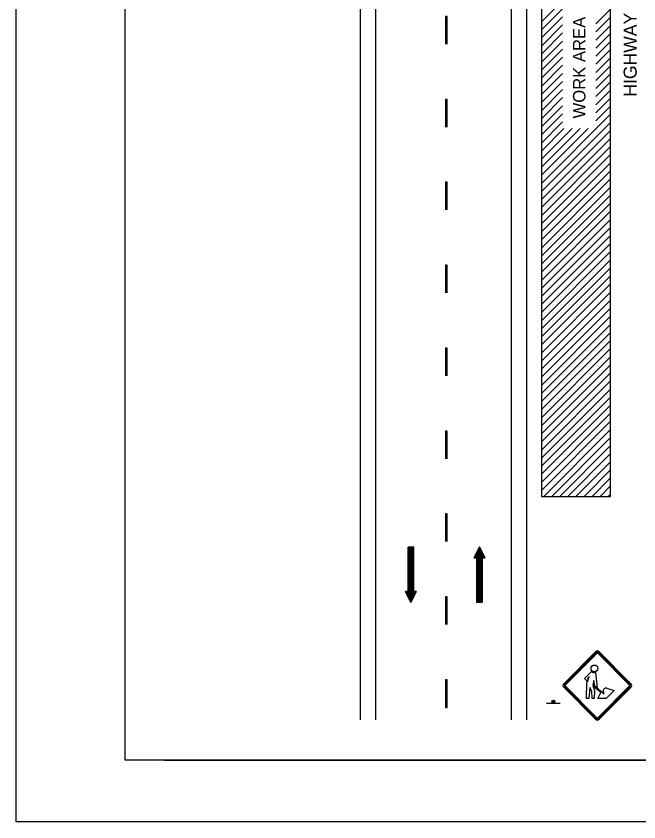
# Model space of a CAD drawing. Extents: x 1342 to 1558, y 178 to 457.
# Drawn here: x 1342.3 to 1451.3, y 177.9 to 318.9 of the extents above; entities that cross this region are included whole.
import ezdxf

# ---------------------------------------------------------------- set-up
doc = ezdxf.new("R2010")
doc.units = 0
for name, color, linetype in [('Level 1', 7, 'Continuous'), ('Level 10', 7, 'Continuous'), ('Level 2', 7, 'Continuous'), ('Level 22', 7, 'Continuous'), ('Level 44', 7, 'Continuous'), ('Level 60', 7, 'Continuous')]:
    doc.layers.add(name, color=color, linetype=linetype)

msp = doc.modelspace()

# ---------------------------------------------------------------- linework, layer by layer
at = {"layer": 'Level 1'}
for p, q in [((1443.76, 207.68), (1438.18, 202.11)), ((1443.88, 207.56), (1438.31, 201.99)), ((1444.01, 207.43), (1438.43, 201.86)), ((1449.72, 201.86), (1444.14, 207.43)), ((1449.84, 201.98), (1444.27, 207.56)), ((1449.96, 202.11), (1444.39, 207.68)), ((1443.81, 205.24), (1443.8, 205.24)), ((1438.43, 201.73), (1444, 196.15)), ((1444.14, 196.15), (1449.72, 201.72)), ((1438.18, 201.48), (1443.76, 195.9)), ((1438.31, 201.6), (1443.88, 196.03)), ((1444.26, 196.03), (1449.84, 201.6)), ((1444.39, 195.9), (1449.96, 201.47))]:
    msp.add_line(p, q, dxfattribs=at)
for points in [[(1442.35, 203.03), (1442.49, 202.92), (1442.33, 202.52), (1441.82, 202.99), (1443.04, 204.25)], [(1442.35, 203.03), (1442.49, 202.92), (1442.33, 202.52), (1441.82, 202.99), (1443.04, 204.25)], [(1442.77, 201.42), (1442.59, 199.52), (1442.16, 199.52), (1442.22, 202.25), (1442.33, 202.52), (1441.82, 202.99), (1443.04, 204.25)], [(1445.71, 201.3), (1446.99, 200.92), (1445.6, 199.52), (1444.15, 199.52), (1444.69, 200.58), (1443.28, 201.73), (1443.56, 201), (1443.52, 199.52), (1443.17, 199.52), (1443.11, 200.78), (1442.77, 201.42), (1442.59, 199.52), (1442.16, 199.52), (1442.22, 202.25), (1442.66, 203.35), (1442.35, 203.03)], [(1445.71, 201.3), (1446.99, 200.92), (1445.6, 199.52), (1444.15, 199.52), (1444.69, 200.58), (1443.28, 201.73), (1443.56, 201), (1443.52, 199.52), (1443.17, 199.52), (1443.11, 200.78), (1442.77, 201.42), (1442.59, 199.52), (1442.16, 199.52), (1442.22, 202.25), (1442.66, 203.35), (1442.35, 203.03)], [(1443.73, 204.07), (1444.02, 201.35), (1443.65, 201.65), (1443.45, 202.66), (1443.28, 201.96), (1445.27, 200.32), (1445.13, 200.67)], [(1443.73, 204.07), (1444.02, 201.35), (1443.65, 201.65), (1443.45, 202.66), (1443.28, 201.96), (1445.27, 200.32), (1445.13, 200.67)], [(1443.73, 204.07), (1444.02, 201.35), (1445.27, 200.32), (1445.13, 200.67)], [(1445.71, 201.3), (1446.99, 200.92), (1445.6, 199.52), (1444.15, 199.52), (1444.69, 200.58), (1443.28, 201.73), (1443.56, 201), (1443.52, 199.52), (1443.17, 199.52), (1443.11, 200.78), (1442.77, 201.42)]]:
    msp.add_lwpolyline(points, dxfattribs=at)
for points in [[(1442.35, 203.03), (1442.49, 202.92), (1442.66, 203.35)], [(1443.65, 201.65), (1443.45, 202.66), (1443.28, 201.96)]]:
    msp.add_lwpolyline(points, close=True, dxfattribs=at)
msp.add_circle((1443.55, 204.78), 0.591, dxfattribs=at)
msp.add_circle((1443.55, 204.78), 0.591, dxfattribs=at)
msp.add_circle((1443.55, 204.78), 0.591, dxfattribs=at)
for centre, radius, start, end in [((1444.07, 207.37), 0.446, 45, 134.9651), ((1444.07, 207.37), 0.27, 45, 134.9651), ((1444.07, 207.37), 0.0948, 45, 134.9651), ((1443.55, 204.78), 0.734, 226.3135, 284.9576), ((1443.55, 204.78), 0.734, 226.3135, 284.9576), ((1443.55, 204.78), 0.734, 226.3135, 284.9576), ((1438.5, 201.79), 0.446, 134.965, 225), ((1438.5, 201.79), 0.27, 134.965, 225), ((1438.5, 201.79), 0.0948, 134.965, 225), ((1449.65, 201.79), 0.0948, 314.9651, 45), ((1449.65, 201.79), 0.27, 314.9651, 45), ((1449.65, 201.79), 0.446, 314.9651, 45), ((1445.57, 200.85), 0.475, 73.381, 201.0999), ((1445.57, 200.85), 0.475, 73.381, 201.0999), ((1445.57, 200.85), 0.475, 73.381, 201.0999), ((1444.07, 196.22), 0.27, 225, 314.9652), ((1444.07, 196.22), 0.0948, 225, 314.9652), ((1444.07, 196.22), 0.446, 225, 314.9652)]:
    msp.add_arc(centre, radius, start, end, dxfattribs=at)
at = {"layer": 'Level 10'}
for p, q in [((1402.52, 373), (1402.52, 195.81)), ((1405.24, 373), (1405.24, 195.81)), ((1428.95, 373), (1428.95, 195.81)), ((1431.69, 373), (1431.69, 195.81)), ((1434.29, 317.96), (1446.38, 330.05)), ((1434.29, 316.54), (1437.98, 320.24)), ((1443.82, 317.59), (1446.38, 320.15)), ((1434.29, 315.13), (1437.98, 318.82)), ((1443.82, 316.18), (1446.38, 318.74)), ((1434.29, 313.71), (1437.98, 317.41)), ((1443.82, 314.76), (1446.38, 317.32)), ((1434.29, 312.3), (1437.98, 316)), ((1443.82, 313.35), (1446.38, 315.91)), ((1434.29, 310.89), (1437.98, 314.58)), ((1443.82, 311.93), (1446.38, 314.5)), ((1434.29, 309.47), (1437.98, 313.17)), ((1443.82, 310.52), (1446.38, 313.08)), ((1434.29, 308.06), (1437.98, 311.75)), ((1434.29, 306.64), (1437.98, 310.34)), ((1443.82, 309.1), (1446.38, 311.67)), ((1434.29, 305.23), (1437.98, 308.93)), ((1443.82, 307.69), (1446.38, 310.25)), ((1434.29, 303.81), (1437.98, 307.51)), ((1443.82, 306.28), (1446.38, 308.84)), ((1434.29, 302.4), (1437.98, 306.1)), ((1443.82, 304.86), (1446.38, 307.42)), ((1434.29, 300.99), (1437.98, 304.68)), ((1443.82, 303.45), (1446.38, 306.01)), ((1434.29, 299.57), (1437.98, 303.27)), ((1443.82, 302.03), (1446.38, 304.6)), ((1434.29, 298.16), (1437.98, 301.86)), ((1443.82, 300.62), (1446.38, 303.18)), ((1434.29, 289.67), (1446.38, 301.77)), ((1434.29, 296.74), (1437.98, 300.44)), ((1434.29, 288.26), (1446.38, 300.35)), ((1434.29, 295.33), (1438.23, 299.27)), ((1434.29, 293.92), (1439.64, 299.27)), ((1434.29, 292.5), (1441.06, 299.27)), ((1434.29, 291.09), (1442.47, 299.27)), ((1434.29, 286.84), (1446.38, 298.94)), ((1434.29, 285.43), (1446.38, 297.53)), ((1434.29, 284.02), (1446.38, 296.11)), ((1434.29, 282.6), (1446.38, 294.7)), ((1434.29, 281.19), (1446.38, 293.28)), ((1434.29, 279.77), (1446.38, 291.87)), ((1434.29, 278.36), (1446.38, 290.45)), ((1434.29, 276.94), (1446.38, 289.04)), ((1434.29, 275.53), (1446.38, 287.62)), ((1434.29, 274.12), (1446.38, 286.21)), ((1434.29, 272.7), (1446.38, 284.8)), ((1434.29, 271.29), (1446.38, 283.38)), ((1434.29, 269.87), (1446.38, 281.97)), ((1434.29, 268.46), (1446.38, 280.55)), ((1434.29, 267.05), (1446.38, 279.14)), ((1434.29, 265.63), (1446.38, 277.73)), ((1434.29, 264.22), (1446.38, 276.31)), ((1434.29, 262.8), (1446.38, 274.9)), ((1434.29, 261.39), (1446.38, 273.48)), ((1434.29, 259.97), (1446.38, 272.07)), ((1434.29, 258.56), (1446.38, 270.66)), ((1434.29, 257.15), (1446.38, 269.24)), ((1434.29, 255.73), (1446.38, 267.83)), ((1434.29, 254.32), (1446.38, 266.41)), ((1434.29, 252.9), (1446.38, 265)), ((1434.29, 251.49), (1446.38, 263.58)), ((1434.29, 250.07), (1446.38, 262.17)), ((1434.29, 248.66), (1446.38, 260.75)), ((1434.29, 247.25), (1446.38, 259.34)), ((1434.29, 245.83), (1446.38, 257.93)), ((1434.29, 244.42), (1446.38, 256.51)), ((1434.29, 243), (1446.38, 255.1)), ((1434.29, 241.59), (1446.38, 253.68)), ((1434.29, 240.18), (1446.38, 252.27)), ((1434.29, 238.76), (1446.38, 250.86)), ((1434.29, 237.35), (1446.38, 249.44)), ((1434.29, 235.93), (1446.38, 248.03)), ((1434.67, 234.9), (1446.38, 246.61)), ((1436.08, 234.9), (1446.38, 245.2)), ((1437.5, 234.9), (1446.38, 243.78)), ((1438.91, 234.9), (1446.38, 242.37)), ((1440.32, 234.9), (1446.38, 240.96)), ((1441.74, 234.9), (1446.38, 239.54)), ((1443.15, 234.9), (1446.38, 238.13)), ((1444.57, 234.9), (1446.38, 236.71)), ((1445.98, 234.9), (1446.38, 235.3)), ((1410.95, 218.26), (1410.95, 226)), ((1411.92, 226), (1410.95, 226)), ((1410.95, 217.29), (1410.95, 226)), ((1411.07, 217.05), (1411.07, 226)), ((1411.19, 216.81), (1411.19, 226)), ((1411.31, 216.57), (1411.31, 226)), ((1411.43, 216.32), (1411.43, 226)), ((1411.55, 216.57), (1411.55, 226)), ((1411.67, 216.81), (1411.67, 226)), ((1411.8, 217.05), (1411.8, 226)), ((1411.92, 218.26), (1411.92, 226)), ((1411.92, 217.29), (1411.92, 226)), ((1423.42, 226.07), (1422.45, 224.13)), ((1423.3, 225.83), (1423.3, 216.39)), ((1423.42, 226.07), (1423.42, 216.39)), ((1423.42, 226.07), (1424.38, 224.13)), ((1423.54, 225.83), (1423.54, 216.39)), ((1422.57, 224.38), (1422.57, 224.13)), ((1422.69, 224.62), (1422.69, 224.13)), ((1422.81, 224.86), (1422.81, 224.13)), ((1422.93, 225.1), (1422.93, 216.39)), ((1423.06, 225.34), (1423.06, 216.39)), ((1423.18, 225.59), (1423.18, 216.39)), ((1423.66, 225.59), (1423.66, 216.39)), ((1423.78, 225.34), (1423.78, 216.39)), ((1423.9, 225.1), (1423.9, 216.39)), ((1424.02, 224.86), (1424.02, 224.13)), ((1424.14, 224.62), (1424.14, 224.13)), ((1424.26, 224.38), (1424.26, 224.13)), ((1422.45, 224.13), (1422.93, 224.13)), ((1422.93, 224.13), (1422.93, 216.39)), ((1423.9, 224.13), (1423.9, 216.39)), ((1423.9, 224.13), (1424.38, 224.13)), ((1411.43, 216.32), (1410.46, 218.26)), ((1410.95, 218.26), (1410.46, 218.26)), ((1410.59, 218.02), (1410.59, 218.26)), ((1410.71, 217.78), (1410.71, 218.26)), ((1410.83, 217.53), (1410.83, 218.26)), ((1411.43, 216.32), (1412.4, 218.26)), ((1412.4, 218.26), (1411.92, 218.26)), ((1412.04, 217.53), (1412.04, 218.26)), ((1412.16, 217.78), (1412.16, 218.26)), ((1412.28, 218.02), (1412.28, 218.26)), ((1422.93, 216.39), (1423.9, 216.39))]:
    msp.add_line(p, q, dxfattribs=at)
at = {"layer": 'Level 2'}
for p, q in [((1417.47, 318.89), (1417.47, 314.06)), ((1417.76, 318.89), (1417.47, 318.89)), ((1417.76, 314.06), (1417.76, 318.89)), ((1417.47, 304.38), (1417.47, 299.54)), ((1417.76, 304.38), (1417.47, 304.38)), ((1417.76, 299.54), (1417.76, 304.38)), ((1417.47, 289.87), (1417.47, 285.03)), ((1417.76, 289.87), (1417.47, 289.87)), ((1417.76, 285.03), (1417.76, 289.87)), ((1417.47, 275.35), (1417.47, 270.51)), ((1417.76, 275.35), (1417.47, 275.35)), ((1417.76, 270.51), (1417.76, 275.35)), ((1417.47, 260.84), (1417.47, 256)), ((1417.76, 260.84), (1417.47, 260.84)), ((1417.76, 256), (1417.76, 260.84)), ((1417.47, 246.33), (1417.47, 241.49)), ((1417.76, 246.33), (1417.47, 246.33)), ((1417.76, 241.49), (1417.76, 246.33)), ((1417.47, 231.81), (1417.47, 226.97)), ((1417.76, 231.81), (1417.47, 231.81)), ((1417.76, 226.97), (1417.76, 231.81)), ((1417.47, 217.3), (1417.47, 212.46)), ((1417.76, 217.3), (1417.47, 217.3)), ((1417.76, 212.46), (1417.76, 217.3)), ((1417.47, 202.78), (1417.47, 197.94)), ((1417.76, 202.78), (1417.47, 202.78)), ((1417.76, 197.94), (1417.76, 202.78)), ((1417.47, 197.94), (1417.76, 197.94))]:
    msp.add_line(p, q, dxfattribs=at)
at = {"layer": 'Level 22'}
msp.add_line((1368.28, 188.73), (1548.28, 188.73), dxfattribs=at)
at = {"layer": 'Level 44'}
msp.add_line((1435.16, 198.72), (1437.58, 198.72), dxfattribs=at)
for radius in [0.242, 0.121]:
    msp.add_circle((1436.37, 198.99), radius, dxfattribs=at)
at = {"layer": 'Level 60'}
msp.add_line((1434.29, 234.9), (1446.38, 234.9), dxfattribs=at)
for points in [[(1342.28, 456.92), (1558.28, 456.92), (1558.28, 177.92), (1342.28, 177.92)], [(1361.41, 446.11), (1548.28, 446.11), (1548.28, 188.73), (1361.41, 188.73)], [(1446.38, 385.84), (1434.29, 385.84), (1434.29, 234.9), (1446.38, 234.9)]]:
    msp.add_lwpolyline(points, close=True, dxfattribs=at)

# ---------------------------------------------------------------- texts
at = {"layer": 'Level 10'}
for s, height, p in [('HIGHWAY R/W', 2.298, (1450.97, 304.85)), ('WORK AREA', 2.177, (1441.98, 301.04))]:
    msp.add_text(s, height=height, rotation=90, dxfattribs=at).set_placement(p)

doc.saveas('drawing.dxf')
